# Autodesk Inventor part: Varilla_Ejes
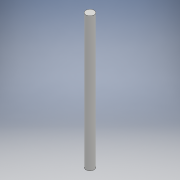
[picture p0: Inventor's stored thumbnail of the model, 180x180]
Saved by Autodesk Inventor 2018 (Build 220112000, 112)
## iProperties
Part Number: Varilla_Ejes
Material: Genérico
Document SubType Name: Modeling
Designer: ULISES
Density: 1 g/cm^3
Appearance: Valor por defecto
Author: ULISES
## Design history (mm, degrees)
sketch "Boceto1"
  geometry: C1 r 4 at (0, 0); 1 further point
  constraints: 1 centre point, 1 coincident
  dimensions: "d0" = 8 diameter of C1
extrude "Extrusión1" new body sketch "Boceto1" distance "d1" = 130; taper "d2" = 0 deg
node "Sólido1"
